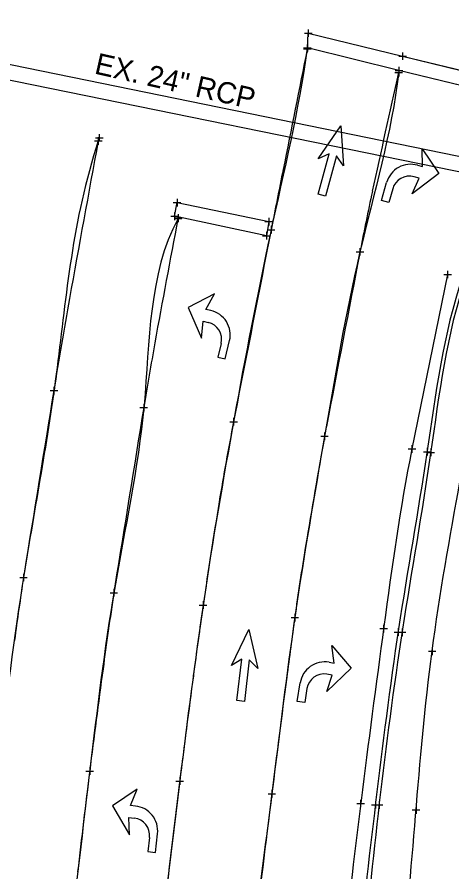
# Model space of a CAD drawing. Extents: x 1324089 to 1329959, y 459099 to 462017.
# Drawn here: x 1324710.1 to 1324767.5, y 459268.6 to 459381.3 of the extents above; entities that cross this region are included whole.
import ezdxf

# ---------------------------------------------------------------- set-up
doc = ezdxf.new("R2010")
doc.units = 0
for name, color, linetype in [('Default', 7, 'Continuous'), ('DR_X_Storm_Sewer', 7, 'Continuous'), ('PM_X_Cells', 7, 'Continuous'), ('PM_X_Channelizing_Line', 7, 'Continuous'), ('PM_X_CL_Double_Solid', 7, 'Continuous'), ('PM_X_Lane_Line', 7, 'Continuous'), ('PM_X_Stop_Line', 7, 'Continuous'), ('PM_X_Surveyed_Line', 7, 'Continuous'), ('PV_X_Curb', 7, 'Continuous'), ('PV_X_EOP', 7, 'Continuous'), ('SV_X_Break_Lines', 7, 'Continuous'), ('SV_X_Shot_Marker', 7, 'Continuous')]:
    doc.layers.add(name, color=color, linetype=linetype)

msp = doc.modelspace()

# ---------------------------------------------------------------- linework, layer by layer
at = {"layer": 'DR_X_Storm_Sewer'}
for p, q in [((1324798.77, 459356.76), (1324681.66, 459380.65)), ((1324798.37, 459354.8), (1324681.26, 459378.69))]:
    msp.add_line(p, q, dxfattribs=at)
at = {"layer": 'PM_X_Cells'}
for p, q in [((1324749.84, 459362.65), (1324752.84, 459367.01)), ((1324752.84, 459367.01), (1324753.18, 459361.73)), ((1324763.61, 459361.62), (1324763.57, 459363.96)), ((1324763.57, 459363.96), (1324765.78, 459360.69)), ((1324749.83, 459357.99), (1324751.29, 459363.29)), ((1324751.29, 459363.29), (1324749.84, 459362.65)), ((1324752.26, 459363.02), (1324750.79, 459357.72)), ((1324753.18, 459361.73), (1324752.26, 459363.02)), ((1324762.97, 459361.8), (1324762.97, 459361.8)), ((1324762.97, 459361.8), (1324763.61, 459361.62)), ((1324765.78, 459360.69), (1324762.26, 459358.01)), ((1324758.21, 459357.15), (1324758.88, 459359.54)), ((1324762.26, 459358.01), (1324763.18, 459360.08)), ((1324763.18, 459360.08), (1324762.51, 459360.27)), ((1324759.68, 459358.67), (1324759.18, 459356.88)), ((1324750.79, 459357.72), (1324749.83, 459357.99)), ((1324759.18, 459356.88), (1324758.21, 459357.15)), ((1324736.18, 459344.82), (1324732.67, 459343.02)), ((1324735.02, 459342.79), (1324736.18, 459344.82)), ((1324732.67, 459343.02), (1324734.45, 459338.98)), ((1324735.66, 459342.64), (1324735.02, 459342.79)), ((1324735.66, 459342.64), (1324735.66, 459342.64)), ((1324734.45, 459338.98), (1324734.65, 459341.23)), ((1324734.65, 459341.23), (1324735.33, 459341.07)), ((1324737.03, 459338.31), (1324736.6, 459336.49)), ((1324737.58, 459336.26), (1324738.15, 459338.67)), ((1324736.6, 459336.49), (1324737.58, 459336.26)), ((1324738.41, 459295.82), (1324740.71, 459300.58)), ((1324740.71, 459300.58), (1324741.86, 459295.42)), ((1324751.94, 459296.14), (1324751.63, 459298.46)), ((1324751.63, 459298.46), (1324754.19, 459295.46)), ((1324739.75, 459296.67), (1324738.41, 459295.82)), ((1324739.12, 459291.2), (1324739.75, 459296.67)), ((1324740.75, 459296.55), (1324740.11, 459291.09)), ((1324741.86, 459295.42), (1324740.75, 459296.55)), ((1324754.19, 459295.46), (1324751, 459292.4)), ((1324751.28, 459296.25), (1324751.28, 459296.25)), ((1324751.28, 459296.25), (1324751.94, 459296.14)), ((1324751.69, 459294.56), (1324750.99, 459294.67)), ((1324751, 459292.4), (1324751.69, 459294.56)), ((1324747.08, 459291.09), (1324747.47, 459293.53)), ((1324748.36, 459292.77), (1324748.07, 459290.93)), ((1324740.11, 459291.09), (1324739.12, 459291.2)), ((1324748.07, 459290.93), (1324747.08, 459291.09)), ((1324725.98, 459279.51), (1324722.7, 459277.32)), ((1324725.06, 459277.37), (1324725.98, 459279.51)), ((1324722.7, 459277.32), (1324724.94, 459273.51)), ((1324725.72, 459277.29), (1324725.06, 459277.37)), ((1324725.72, 459277.29), (1324725.72, 459277.29)), ((1324724.94, 459273.51), (1324724.87, 459275.78)), ((1324724.87, 459275.78), (1324725.57, 459275.7)), ((1324727.59, 459273.15), (1324727.37, 459271.3)), ((1324728.36, 459271.18), (1324728.65, 459273.64)), ((1324727.37, 459271.3), (1324728.36, 459271.18))]:
    msp.add_line(p, q, dxfattribs=at)
for centre, radius, start, end in [((1324762.04, 459358.65), 3.28, 73.5099, 164.4184), ((1324761.89, 459358.06), 2.3, 74.4184, 164.4184), ((1324734.96, 459339.43), 3.28, 346.6429, 77.5514), ((1324734.8, 459338.84), 2.3, 346.6429, 76.6429), ((1324750.71, 459293.02), 3.28, 80.0227, 170.9311), ((1324750.63, 459292.41), 2.3, 80.9311, 170.9311), ((1324725.39, 459274.02), 3.28, 353.3461, 84.2546), ((1324725.31, 459273.41), 2.3, 353.3461, 83.3461)]:
    msp.add_arc(centre, radius, start, end, dxfattribs=at)
at = {"layer": 'PM_X_Channelizing_Line'}
for p, q in [((1324748.42, 459377.28), (1324748.4, 459377.15)), ((1324760.5, 459374.28), (1324760.47, 459374.02))]:
    msp.add_line(p, q, dxfattribs=at)
for centre, radius, start, end in [((1334621.31, 457390.37), 10070.82, 168.622012, 168.71427), ((1326143.78, 459058.66), 1418.81, 167.15777, 167.80539), ((1327216.78, 458868.02), 2520.3, 168.71427, 168.89869), ((1325114.45, 459281.11), 365.71, 167.8054, 169.081), ((1570224.28, 411186.08), 250161.6, 168.8986909, 168.9044017), ((1361970.39, 452171.1), 37901.19, 169.081004, 169.116491), ((1325138.74, 459250.69), 407.46, 169.0671, 170.5771), ((1325041.15, 459269.54), 308.06, 168.9044, 169.0671), ((1324864.21, 459305.55), 115.37, 169.1165, 169.7597), ((1325658.75, 459162.01), 922.76, 169.75972, 170.67268), ((1325397.21, 459207.79), 669.46, 170.57709, 171.75506), ((1325131.31, 459248.64), 388.26, 170.6727, 172.0802), ((1325519.36, 459190.09), 792.89, 171.75506, 172.4356), ((1325656.84, 459175.54), 918.85, 172.08015, 172.57444), ((1326469.51, 459063.92), 1751.38, 172.4356, 172.89349), ((1328230.36, 458840.13), 3514.13, 172.57444, 172.8272), ((1326509.98, 459058.87), 1792.17, 172.89349, 173.4467), ((1328296.28, 458831.83), 3580.57, 172.8272, 173.13986)]:
    msp.add_arc(centre, radius, start, end, dxfattribs=at)
at = {"layer": 'PM_X_CL_Double_Solid'}
msp.add_line((1324731.38, 459354.85), (1324731.35, 459354.79), dxfattribs=at)
for centre, radius, start, end in [((1326430.74, 459029.65), 1730.22, 169.16876, 169.72136), ((1325186.46, 459255.3), 465.63, 169.7214, 170.7866), ((1374728.2, 451219.39), 50654.88, 170.78659, 170.81358), ((1325478.13, 459193.09), 763.56, 171.54009, 172.30048), ((1324792.03, 459295.14), 69.91, 170.8136, 171.5401), ((1326085.77, 459110.94), 1376.73, 172.30048, 172.86676), ((1325936.89, 459129.57), 1226.69, 172.86676, 173.49221)]:
    msp.add_arc(centre, radius, start, end, dxfattribs=at)
at = {"layer": 'PM_X_Lane_Line'}
msp.add_line((1324720.96, 459365.41), (1324720.83, 459365.01), dxfattribs=at)
for centre, radius, start, end in [((1327176.08, 458906.71), 2497.66, 169.42701, 169.91146), ((1325554.46, 459195.23), 850.58, 169.91146, 170.74161), ((1410619.98, 445328.65), 87038.89, 170.7416084, 170.757705), ((1324750.32, 459301.56), 39.8, 170.7577, 171.5105), ((1325357.86, 459210.87), 654.07, 171.51048, 172.24546)]:
    msp.add_arc(centre, radius, start, end, dxfattribs=at)
at = {"layer": 'PM_X_Stop_Line'}
for p, q in [((1324748.42, 459377.28), (1324748.53, 459379.22)), ((1324748.53, 459379.22), (1324760.98, 459376.18)), ((1324760.5, 459374.28), (1324748.42, 459377.28)), ((1324760.98, 459376.18), (1324776.46, 459372.42)), ((1324776.12, 459370.51), (1324760.5, 459374.28)), ((1324730.9, 459355.07), (1324731.23, 459356.87)), ((1324731.23, 459356.87), (1324743.32, 459354.36)), ((1324743.01, 459352.51), (1324730.9, 459355.07)), ((1324743.32, 459354.36), (1324743.01, 459352.51))]:
    msp.add_line(p, q, dxfattribs=at)
for points in [[(1324776.46, 459372.42), (1324776.12, 459370.51), (1324760.5, 459374.28), (1324748.42, 459377.28), (1324748.53, 459379.22), (1324760.98, 459376.18)], [(1324743.32, 459354.36), (1324743.01, 459352.51), (1324730.9, 459355.07), (1324731.23, 459356.87)]]:
    msp.add_lwpolyline(points, close=True, dxfattribs=at)
at = {"layer": 'PM_X_Surveyed_Line'}
for p, q in [((1324748.42, 459377.28), (1324748.4, 459377.15)), ((1324760.5, 459374.28), (1324760.47, 459374.02)), ((1324720.96, 459365.41), (1324720.83, 459365.01)), ((1324731.38, 459354.85), (1324731.35, 459354.79))]:
    msp.add_line(p, q, dxfattribs=at)
for points in [[(1324748.4, 459377.15), (1324747.28, 459369.15), (1324743.34, 459352.83), (1324738.67, 459328.42), (1324734.54, 459304.18), (1324731.59, 459280.68), (1324728.73, 459257.83), (1324727.42, 459237.03), (1324726.49, 459223.95), (1324726.12, 459218.35)], [(1324760.47, 459374.02), (1324759.54, 459366.01), (1324754.82, 459350.28), (1324750.73, 459326.23), (1324746.58, 459302.44), (1324743.83, 459279.19), (1324740.78, 459256.73), (1324739.54, 459236.59), (1324738.54, 459223.99), (1324738.15, 459218.69)], [(1324720.83, 459365.01), (1324717.36, 459354.42), (1324715.9, 459334.74), (1324710.69, 459307.46), (1324707.68, 459283.27), (1324704.59, 459259.48), (1324702.8, 459238.34), (1324702.05, 459224.84), (1324701.82, 459219.29)], [(1324731.35, 459354.79), (1324727.41, 459347.41), (1324727.87, 459329.65), (1324722.53, 459305.88), (1324719.73, 459282), (1324716.91, 459258.82), (1324715.19, 459237.67), (1324714.33, 459224.27), (1324714.01, 459218.52)]]:
    msp.add_open_spline(points, degree=3, dxfattribs=at)
at = {"layer": 'PV_X_Curb'}
for points in [[(1324768.88, 459347), (1324766.33, 459339.61), (1324764.41, 459323.73), (1324760.23, 459300.65), (1324757.38, 459277.59), (1324754.8, 459255.45), (1324752.99, 459235.62), (1324751.94, 459223.26), (1324751.52, 459217.98)], [(1324769.34, 459346.95), (1324766.74, 459339.56), (1324764.89, 459323.67), (1324760.8, 459300.59), (1324757.77, 459277.56), (1324755.59, 459255.42), (1324753.47, 459235.57), (1324752.44, 459223.18), (1324752.02, 459217.82)]]:
    msp.add_open_spline(points, degree=3, dxfattribs=at)
at = {"layer": 'PV_X_EOP'}
msp.add_line((1324766.93, 459347.39), (1324762.22, 459324.38), dxfattribs=at)
msp.add_open_spline([(1324762.22, 459324.38), (1324760.62, 459316.54), (1324758.5, 459300.92), (1324755.42, 459277.89), (1324752.85, 459255.64), (1324750.92, 459235.77), (1324749.88, 459223.34), (1324749.48, 459218.03)], degree=3, dxfattribs=at)
at = {"layer": 'SV_X_Break_Lines'}
msp.add_open_spline([(1324758.84, 459218.38), (1324759.03, 459223.35), (1324758.93, 459236.5), (1324761.05, 459255.91), (1324762.78, 459277.36), (1324764.69, 459298.91), (1324768.89, 459321.85), (1324772.52, 459342.12), (1324779.19, 459358.73), (1324789.11, 459371.52), (1324804.35, 459377.96), (1324821.07, 459383.64), (1324841.95, 459386.23), (1324864.43, 459389.81), (1324886.84, 459390.45), (1324905.55, 459391.13), (1324922.61, 459391.44), (1324932.95, 459392.39), (1324937.78, 459392.93)], degree=3, dxfattribs=at)
at = {"layer": 'SV_X_Shot_Marker'}
for p, q in [((1324748.53, 459379.72), (1324748.53, 459378.72)), ((1324748.03, 459379.22), (1324749.03, 459379.22)), ((1324748.53, 459379.22), (1324748.53, 459379.22)), ((1324748.4, 459377.65), (1324748.4, 459376.65)), ((1324748.42, 459377.78), (1324748.42, 459376.78)), ((1324748.42, 459377.78), (1324748.42, 459376.78)), ((1324747.9, 459377.15), (1324748.9, 459377.15)), ((1324747.92, 459377.28), (1324748.92, 459377.28)), ((1324747.92, 459377.28), (1324748.92, 459377.28)), ((1324748.4, 459377.15), (1324748.4, 459377.15)), ((1324748.42, 459377.28), (1324748.42, 459377.28)), ((1324748.42, 459377.28), (1324748.42, 459377.28)), ((1324760.98, 459376.68), (1324760.98, 459375.68)), ((1324760.48, 459376.18), (1324761.48, 459376.18)), ((1324760.98, 459376.18), (1324760.98, 459376.18)), ((1324760, 459374.28), (1324761, 459374.28)), ((1324760, 459374.28), (1324761, 459374.28)), ((1324760.47, 459374.52), (1324760.47, 459373.52)), ((1324760.5, 459374.78), (1324760.5, 459373.78)), ((1324760.5, 459374.78), (1324760.5, 459373.78)), ((1324760.5, 459374.28), (1324760.5, 459374.28)), ((1324760.5, 459374.28), (1324760.5, 459374.28)), ((1324759.97, 459374.02), (1324760.97, 459374.02)), ((1324760.47, 459374.02), (1324760.47, 459374.02)), ((1324720.46, 459365.41), (1324721.46, 459365.41)), ((1324720.83, 459365.51), (1324720.83, 459364.51)), ((1324720.96, 459365.91), (1324720.96, 459364.91)), ((1324720.96, 459365.41), (1324720.96, 459365.41)), ((1324720.33, 459365.01), (1324721.33, 459365.01)), ((1324720.83, 459365.01), (1324720.83, 459365.01)), ((1324731.23, 459357.37), (1324731.23, 459356.37)), ((1324730.73, 459356.87), (1324731.73, 459356.87)), ((1324731.23, 459356.87), (1324731.23, 459356.87)), ((1324730.4, 459355.07), (1324731.4, 459355.07)), ((1324730.9, 459355.57), (1324730.9, 459354.57)), ((1324730.9, 459355.07), (1324730.9, 459355.07)), ((1324731.35, 459355.29), (1324731.35, 459354.29)), ((1324731.38, 459355.35), (1324731.38, 459354.35)), ((1324730.85, 459354.79), (1324731.85, 459354.79)), ((1324730.88, 459354.85), (1324731.88, 459354.85)), ((1324731.35, 459354.79), (1324731.35, 459354.79)), ((1324731.38, 459354.85), (1324731.38, 459354.85)), ((1324742.82, 459354.36), (1324743.82, 459354.36)), ((1324743.32, 459354.86), (1324743.32, 459353.86)), ((1324743.32, 459354.36), (1324743.32, 459354.36)), ((1324743.64, 459353.79), (1324743.64, 459352.79)), ((1324743.01, 459353.01), (1324743.01, 459352.01)), ((1324743.14, 459353.29), (1324744.14, 459353.29)), ((1324743.64, 459353.29), (1324743.64, 459353.29)), ((1324742.51, 459352.51), (1324743.51, 459352.51)), ((1324743.01, 459352.51), (1324743.01, 459352.51)), ((1324754.86, 459350.38), (1324755.86, 459350.38)), ((1324755.36, 459350.88), (1324755.36, 459349.88)), ((1324755.36, 459350.38), (1324755.36, 459350.38)), ((1324766.43, 459347.39), (1324767.43, 459347.39)), ((1324766.93, 459347.89), (1324766.93, 459346.89)), ((1324766.93, 459347.39), (1324766.93, 459347.39)), ((1324714.97, 459332.58), (1324714.97, 459331.58)), ((1324714.47, 459332.08), (1324715.47, 459332.08)), ((1324714.97, 459332.08), (1324714.97, 459332.08)), ((1324726.83, 459330.35), (1324726.83, 459329.35)), ((1324726.33, 459329.85), (1324727.33, 459329.85)), ((1324726.83, 459329.85), (1324726.83, 459329.85)), ((1324738.18, 459327.97), (1324739.18, 459327.97)), ((1324738.68, 459328.47), (1324738.68, 459327.47)), ((1324738.68, 459327.97), (1324738.68, 459327.97)), ((1324750.18, 459326.06), (1324751.18, 459326.06)), ((1324750.68, 459326.56), (1324750.68, 459325.56)), ((1324750.68, 459326.06), (1324750.68, 459326.06)), ((1324762.22, 459324.88), (1324762.22, 459323.88)), ((1324764.22, 459324.52), (1324764.22, 459323.52)), ((1324761.72, 459324.38), (1324762.72, 459324.38)), ((1324762.22, 459324.38), (1324762.22, 459324.38)), ((1324763.72, 459324.02), (1324764.72, 459324.02)), ((1324764.19, 459323.93), (1324765.19, 459323.93)), ((1324764.22, 459324.02), (1324764.22, 459324.02)), ((1324764.69, 459324.43), (1324764.69, 459323.43)), ((1324764.69, 459323.93), (1324764.69, 459323.93)), ((1324710.96, 459307.93), (1324710.96, 459306.93)), ((1324710.46, 459307.43), (1324711.46, 459307.43)), ((1324710.96, 459307.43), (1324710.96, 459307.43)), ((1324722.38, 459305.42), (1324723.38, 459305.42)), ((1324722.88, 459305.92), (1324722.88, 459304.92)), ((1324722.88, 459305.42), (1324722.88, 459305.42)), ((1324734.66, 459304.3), (1324734.66, 459303.3)), ((1324734.16, 459303.8), (1324735.16, 459303.8)), ((1324734.66, 459303.8), (1324734.66, 459303.8)), ((1324746.26, 459302.14), (1324747.26, 459302.14)), ((1324746.76, 459302.64), (1324746.76, 459301.64)), ((1324746.76, 459302.14), (1324746.76, 459302.14)), ((1324758.48, 459301.19), (1324758.48, 459300.19)), ((1324757.98, 459300.69), (1324758.98, 459300.69)), ((1324758.48, 459300.69), (1324758.48, 459300.69)), ((1324759.89, 459300.24), (1324760.89, 459300.24)), ((1324760.39, 459300.74), (1324760.39, 459299.74)), ((1324760.39, 459300.24), (1324760.39, 459300.24)), ((1324760.42, 459300.2), (1324761.42, 459300.2)), ((1324760.92, 459300.7), (1324760.92, 459299.7)), ((1324760.92, 459300.2), (1324760.92, 459300.2)), ((1324764.39, 459297.7), (1324765.39, 459297.7)), ((1324764.89, 459298.2), (1324764.89, 459297.2)), ((1324764.89, 459297.7), (1324764.89, 459297.7)), ((1324719.2, 459281.9), (1324720.2, 459281.9)), ((1324719.7, 459282.4), (1324719.7, 459281.4)), ((1324719.7, 459281.9), (1324719.7, 459281.9)), ((1324731.08, 459280.59), (1324732.08, 459280.59)), ((1324731.58, 459281.09), (1324731.58, 459280.09)), ((1324731.58, 459280.59), (1324731.58, 459280.59)), ((1324743.73, 459279.41), (1324743.73, 459278.41)), ((1324743.23, 459278.91), (1324744.23, 459278.91)), ((1324743.73, 459278.91), (1324743.73, 459278.91)), ((1324754.95, 459277.62), (1324755.95, 459277.62)), ((1324755.45, 459278.12), (1324755.45, 459277.12)), ((1324755.45, 459277.62), (1324755.45, 459277.62)), ((1324756.89, 459277.45), (1324757.89, 459277.45)), ((1324757.38, 459277.43), (1324758.38, 459277.43)), ((1324757.39, 459277.95), (1324757.39, 459276.95)), ((1324757.39, 459277.45), (1324757.39, 459277.45)), ((1324757.88, 459277.93), (1324757.88, 459276.93)), ((1324757.88, 459277.43), (1324757.88, 459277.43)), ((1324762.76, 459277.28), (1324762.76, 459276.28)), ((1324762.26, 459276.78), (1324763.26, 459276.78)), ((1324762.76, 459276.78), (1324762.76, 459276.78))]:
    msp.add_line(p, q, dxfattribs=at)

# ---------------------------------------------------------------- texts
at = {"layer": 'Default'}
msp.add_text('EX. 24" RCP', height=2.8, rotation=347.2355, dxfattribs=at).set_placement((1324720.2, 459373.91))

doc.saveas('drawing.dxf')
